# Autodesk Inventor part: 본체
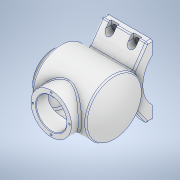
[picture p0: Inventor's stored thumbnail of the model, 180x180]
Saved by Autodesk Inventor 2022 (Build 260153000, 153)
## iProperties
Created: 2023-04
Part Number: 본체
Material: 알루미늄 6061
Document SubType Name: Modeling
Designer: Admin
Mass: 1296.71 g
Surface Area: 1060.45 cm^2
Volume: 480.264 cm^3
Density: 2.7 g/cm^3
Appearance: 알루미늄 - 평지
Author: Admin
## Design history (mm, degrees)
sketch "스케치1"
  geometry: L1 (0, 27)-(19, 27); L2 (19, 27)-(19, 43); L3 (19, 43)-(103.887, 43); L4 (0, 27)-(0, 36); L5 (0, 36)-(12, 36); L6 (12, 36)-(12, 50); L7 (12, 50)-(108.336, 50); L8 (-24.575, 0)-(147.453, 0) reference; L9 (0, -10.134)-(0, 60.805) reference; L10 (113, 0)-(120, 0); A1 r 106 centre (7, 0) between (113, 0) and (103.887, 43); A2 r 113 centre (7, 0) between (120, 0) and (108.336, 50); 2 further points
  constraints: 16 end point, 5 perpendicular, 4 point on circle, 4 point on line, 2 centre point, 1 coincident, 1 collinear, 1 horizontal, 1 midpoint, 1 vertical
  dimensions: "d0" = 113 radius of A2; "d1" = 7 radial gap between concentric circles of A2 A1; "d2" = 120 horizontal distance of L10.end L4.end; "d3" = 108 horizontal distance of L10.end L6.end; "d4" = 54 diameter of L1 L8; "d5" = 86 diameter of L3 L8; "d6" = 100 diameter of L7 L8; "d7" = 72 diameter of L5 L8; "d8" = 19 distance of L1.start L1.end
revolve "회전1" sketch "스케치1" stored, may be unused: angle "d9" = 90 deg
node "작업 평면1"
sketch "스케치2"
  geometry: L1 (0, -70)-(0, 70) reference; L2 (-70, 0)-(70, 0) reference; L3 (26.694, -42.278)-(62, -67); L4 (62, -67)-(62, -77); L5 (62, -77)-(38.5, -77); L6 (-26.694, -42.278)-(-62, -67); L7 (-62, -67)-(-62, -77); L8 (-62, -77)-(-38.5, -77); A1 r 52.096 centre (0, -112.096) between (38.5, -77) and (-38.5, -77); 4 further points
  constraints: 12 end point, 4 symmetric about line, 3 point on circle, 2 vertical, 1 centre point, 1 perpendicular, 1 point on line, 5 other
  dimensions: "d11" = 10 distance of L3.end L4.end; "d12" = 55 deg angle of L3 L4; "d13" = 77 distance of L8.end L5.end; "d14" = 17 distance from line of L8 point (0, -60); "d15" = 77 distance between parallel lines of L8 L2; "d16" = 124 distance between parallel lines of L7 L4
extrude "돌출1" join sketch "스케치2" distance "d17" = 80; taper "d18" = 0 deg
node "작업 평면3"
sketch "스케치3"
  geometry: L1 (20, 38.5)-(20, 62) reference; L2 (20, 62)-(100, 62) reference; L3 (100, 38.5)-(100, 62) reference; L4 (20, 38.5)-(100, 38.5) reference; L5 (20, -62)-(20, -38.5) reference; L6 (20, -38.5)-(100, -38.5) reference; L7 (100, -62)-(100, -38.5) reference; L8 (20, -62)-(100, -62) reference; L9 (0, -86.8)-(0, 86.8) reference; L10 (-24, 0)-(144, 0) reference; L11 (87, -54)-(87, -62); L12 (20, -62)-(100, -62) reference; L13 (73, -54)-(73, -62); L14 (47, -54)-(47, -62); L15 (33, -54)-(33, -62); A1 r 7 centre (80, -54) between (87, -54) and (73, -54); A2 r 7 centre (40, -54) between (47, -54) and (33, -54); 3 further points
  constraints: 8 end point, 4 point on circle, 4 point on line, 4 tangent, 3 perpendicular, 2 centre point, 2 coincident, 1 horizontal alignment, 1 vertical
  dimensions: "d20" = 20 distance from line of point (80, -54) L7; "d21" = 40 distance of point (40, -54) point (80, -54); "d22" = 8 distance from line of L8 point (80, -54); "d23" = 14 diameter of A1; "d24" = 14 diameter of A2
extrude "돌출2" cut sketch "스케치3" stored distance "d25" = 80; taper "d26" = 0 deg
sketch "스케치4"
  geometry: C1 r 4.5 at (40, -54); C2 r 4.5 at (80, -54); A1 r 7 centre (40, -54) between (47, -54) and (33, -54) reference; A2 r 7 centre (80, -54) between (87, -54) and (73, -54) reference; 1 further point
  constraints: 2 centre point, 2 coincident
  dimensions: "d27" = 9 diameter of C1; "d28" = 9 diameter of C2
extrude "돌출3" cut sketch "스케치4" extent not by distance; stored distance "d29" = 0; taper "d30" = 0 deg
node "작업 평면4"
sketch "스케치5"
  geometry: L1 (0, -70)-(0, 70) reference; L2 (-24, 0)-(144, 0) reference; C1 r 36 at (62, 0); 1 further point
  constraints: 1 centre point, 1 point on line
  dimensions: "d32" = 72 diameter of C1; "d33" = 62 distance from line of L1 C1.centre
extrude "돌출4" join sketch "스케치5" stored distance "d34" = 10; taper "d35" = 0 deg
sketch "스케치6"
  geometry: L1 (-86, 0)-(82, 0) reference; L2 (-62, -86.8)-(-62, 86.8) reference; C1 r 36 at (0, 0) reference; C2 r 27 at (0, 0); 1 further point
  constraints: 1 centre point, 1 coincident
  dimensions: "d36" = 54 diameter of C2
extrude "돌출5" cut sketch "스케치6" stored distance "d37" = 10; taper "d38" = 0 deg
sketch "스케치7" dims "d39" = 65
  geometry: L1 (-70, 0)-(70, 0) reference; C1 r 27 at (0, 0) reference; C2 r 36 at (0, 0) reference; 3 further points
  constraints: 1 coincident, 1 horizontal alignment, 1 point on line, 2 other
hole "구멍1" sketch "스케치7" at (32.5, 0) diameter "d40" = 3.242; stored, may be unused: countersink angle "d44" = 90 deg, drill point angle "d46" = 118 deg; dims "d41" = 8, "d42" = 4, "d43" = 2, "d45" = 10
sketch "스케치8" dims "d50" = 65
  geometry: L1 (-86, 0)-(82, 0) reference; C1 r 27 at (0, 0) reference; C2 r 36 at (0, 0) reference; 3 further points
  constraints: 1 coincident, 1 horizontal alignment, 1 point on line, 2 other
hole "구멍2" sketch "스케치8" at (32.5, 0) diameter "d51" = 3.242; stored, may be unused: countersink angle "d55" = 90 deg, drill point angle "d57" = 118 deg; dims "d52" = 8, "d53" = 4, "d54" = 2, "d56" = 10
node "작업 평면5"
sketch "스케치9"
  geometry: L1 (-60.168, -36)-(-60.168, 36) reference; L2 (-84.168, 0)-(83.832, 0) reference; 2 further points
  constraints: 1 point on line, 1 other
  dimensions: "d62" = 62 distance from line of point (1.832, 0) L1
feature "엠보싱1" sketch "스케치9" dims "d0" = 113, "d1" = 7, "d2" = 120, "d3" = 108, "d4" = 54, "d5" = 86, "d6" = 100, "d7" = 72, "d8" = 19, "d63" = 0.5, "d64" = 0
fillet "모깎기1" dims "d65" = 3
chamfer "모따기1" distance "d66" = 1; stored, may be unused: second distance "d67" = 2, angle "d68" = 45 deg
node "솔리드1"
mirror "미러1"
pattern_circular "원형 패턴1" dims angle "d48" = 360 deg
pattern_circular "원형 패턴2" dims angle "d59" = 360 deg
node "투영된 루프1"
node "투영된 루프2"
node "투영된 루프3"
node "투영된 루프4"
node "투영된 루프5"
feature "A9D066F2-1C7D-4E18-AEED-F7BC21143FA4" dims "d40" = 3.242, "d41" = 8, "d42" = 4, "d43" = 2, "d44" = 90 deg, "d45" = 10, "d46" = 118 deg
other parameters: "d19" = -71, "d31" = 65
